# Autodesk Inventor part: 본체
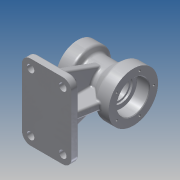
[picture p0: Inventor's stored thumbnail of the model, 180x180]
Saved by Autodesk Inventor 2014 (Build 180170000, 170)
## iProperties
Created: 2015-08
Part Number: 본체
Material: 알루미늄 6061
Document SubType Name: Modeling
Designer: SDA20
Density: 2.71 g/cm^3
Appearance: 알루미늄 - 평지
Mass: 1061.81 g
Surface Area: 751.05 cm^2
Volume: 391.813 cm^3
Author: SDA20
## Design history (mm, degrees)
sketch "스케치1"
  geometry: L1 (-574.06, -1.519)-(-484.06, -1.519); L2 (-574.06, -1.519)-(-574.06, 33.481); L3 (-574.06, 33.481)-(-554.06, 33.481); L4 (-554.06, 33.481)-(-548.864, 24.481); L5 (-548.864, 24.481)-(-520.745, 24.481); L6 (-520.745, 24.481)-(-504.06, 38.481); L7 (-504.06, 38.481)-(-484.06, 38.481); L8 (-484.06, 38.481)-(-484.06, -1.519)
  constraints: 16 end point, 3 parallel, 2 perpendicular, 1 horizontal
  dimensions: "d7" = 90 distance of L1.start L1.end; "d8" = 35 distance of L1.start L2.end; "d9" = 20 distance of L2.end L3.end; "d10" = 80 diameter of L7 L1; "d11" = 52 diameter of L5 L1; "d14" = 20 distance of L6.end L7.end
revolve "회전1" sketch "스케치1" stored, may be unused: angle "d17" = 90 deg
sketch "스케치2"
  geometry: C1 r 40 at (0, 0) reference; C2 r 26 at (0, 0)
  constraints: 1 centre point, 1 coincident
  dimensions: "d18" = 52 diameter of C2
extrude "돌출1" cut sketch "스케치2" distance "d19" = 20; taper "d20" = 0 deg
sketch "스케치3"
  geometry: C1 r 26 at (0, 0) reference; C2 r 19 at (0, 0)
  constraints: 1 centre point, 1 coincident
  dimensions: "d21" = 38 diameter of C2
extrude "돌출2" cut sketch "스케치3" distance "d22" = 3; taper "d23" = 0 deg
sketch "스케치4"
  geometry: C1 r 35 at (0, 0) reference; C2 r 20 at (0, 0)
  constraints: 1 centre point, 1 coincident
  dimensions: "d24" = 40 diameter of C2
extrude "돌출3" cut sketch "스케치4" distance "d25" = 17; taper "d26" = 0 deg
sketch "스케치5"
  geometry: C1 r 20 at (0, 0) reference; C2 r 16 at (0, 0)
  constraints: 1 centre point, 1 coincident
  dimensions: "d27" = 32 diameter of C2
extrude "돌출4" cut sketch "스케치5" stored distance "d28" = 17; taper "d29" = 0 deg
chamfer "모따기1" distance "d30" = 1; stored, may be unused: second distance "d31" = 2, angle "d32" = 45 deg
fillet "모깎기1" dims "d33" = 0.3
fillet "모깎기2" dims "d34" = 3
fillet "모깎기3" dims "d35" = 5
fillet "모깎기4" dims "d36" = 5
sketch "스케치6"
  geometry: L1 (0, 0)-(0, 27); C1 r 21 at (0, 0) reference; C2 r 27 at (0, 0)
  constraints: 2 end point, 1 centre point, 1 coincident, 1 vertical
  dimensions: "d37" = 54 diameter of C2; "d38" = 27 distance of L1.start L1.end
hole "구멍1" sketch "스케치6" at (0, 27) diameter "d39" = 3.459; stored, may be unused: countersink angle "d43" = 90 deg, drill point angle "d45" = 118 deg; dims "d40" = 10, "d41" = 4, "d42" = 2, "d44" = 13
sketch "스케치7"
  geometry: L1 (0, 0)-(0, 33); C1 r 27 at (0, 0) reference; C2 r 33 at (0, 0)
  constraints: 2 end point, 1 centre point, 1 coincident, 1 vertical
  dimensions: "d49" = 66 diameter of C2; "d50" = 33 distance of L1.start L1.end
hole "구멍2" sketch "스케치7" at (0, 33) diameter "d51" = 3.459; stored, may be unused: countersink angle "d55" = 90 deg, drill point angle "d57" = 118 deg; dims "d52" = 10, "d53" = 4, "d54" = 2, "d56" = 13
node "작업 평면1"
node "스케치8"
sketch "스케치9"
  geometry: L1 (-574.06, -36.519)-(-574.06, 33.481) reference; L2 (-574.06, -91.519)-(-494.06, -91.519); L3 (-494.06, -91.519)-(-494.06, -79.519); L4 (-494.06, -79.519)-(-574.06, -79.519); L5 (-574.06, -79.519)-(-574.06, -91.519)
  constraints: 8 end point, 2 perpendicular
  dimensions: "d62" = 80 distance of L2.start L2.end; "d63" = 12 distance of L2.end L3.end; "d64" = 80 distance of L3.end L4.end
extrude "돌출5" join sketch "스케치9" stored distance "d65" = 122; taper "d66" = 0 deg
node "작업 평면2"
sketch "스케치10"
  geometry: L1 (122, 12)-(122, 0) reference; L2 (122, 0)-(0, 0) reference; L3 (0, 0)-(0, 12) reference; L4 (0, 12)-(122, 12) reference; L5 (0, 12)-(10, 12); L6 (10, 12)-(37.923, 88.718); L7 (112, 12)-(84.077, 88.718); L8 (10, 12)-(112, 12); L9 (84.077, 88.718)-(71.095, 70.606); L10 (71.095, 70.606)-(51.998, 70.606); L11 (51.998, 70.606)-(37.923, 88.718); C1 r 26 at (61, 90) reference; C2 r 16 at (61, 90) reference
  constraints: 14 end point, 1 point on line
  dimensions: "d67" = 10 distance of L3.end L5.end; "d69" = 70 deg angle of L4 L6
extrude "돌출6" join sketch "스케치10" stored distance "d70" = 12; taper "d71" = 0 deg
node "작업 평면3"
sketch "스케치13"
  geometry: L1 (504.06, -27.219)-(504.06, -20.519) reference; L2 (504.06, -20.519)-(507.06, -20.519) reference; L3 (507.06, -20.519)-(507.06, -17.519) reference; L4 (507.06, -17.519)-(554.06, -17.519) reference; L5 (557.06, -20.519)-(557.06, -21.219) reference; L6 (557.36, -21.519)-(573.06, -21.519) reference; L7 (573.06, -21.519)-(574.06, -22.519) reference; L8 (574.06, -22.519)-(574.06, -36.519) reference; L9 (574.06, -36.519)-(556.947, -36.519) reference; L10 (552.617, -34.019)-(550.307, -30.019) reference; L11 (545.977, -27.519)-(540.06, -27.519) reference; L12 (540.06, -27.519)-(540.06, -79.519) reference; L13 (540.06, -79.519)-(574.06, -79.519) reference; L14 (574.06, -79.519)-(574.06, -91.519) reference; L15 (574.06, -91.519)-(494.06, -91.519) reference; L16 (494.06, -91.519)-(494.06, -79.519) reference; L17 (494.06, -79.519)-(528.06, -79.519) reference; L18 (528.06, -79.519)-(528.06, -27.519) reference; L19 (528.06, -27.519)-(522.564, -27.519) reference; L20 (519.351, -28.689)-(505.454, -40.349) reference; L21 (502.24, -41.519)-(484.06, -41.519) reference; L22 (484.06, -41.519)-(484.06, -28.519) reference; L23 (484.06, -28.519)-(485.06, -27.519) reference; L24 (485.06, -27.519)-(503.76, -27.519) reference; L25 (503.76, 24.481)-(485.06, 24.481) reference; L26 (485.06, 24.481)-(484.06, 25.481) reference; L27 (484.06, 25.481)-(484.06, 29.751) reference; L28 (484.06, 29.751)-(497.06, 29.751) reference; L29 (497.06, 29.751)-(498.099, 31.481) reference; L30 (498.099, 31.481)-(497.06, 33.21) reference; L31 (497.06, 33.21)-(484.06, 33.21) reference; L32 (484.06, 33.21)-(484.06, 38.481) reference; L33 (484.06, 38.481)-(502.24, 38.481) reference; L34 (505.454, 37.311)-(519.351, 25.651) reference; L35 (522.564, 24.481)-(545.977, 24.481) reference; L36 (550.307, 26.981)-(552.617, 30.981) reference; L37 (556.947, 33.481)-(574.06, 33.481) reference; L38 (574.06, 33.481)-(574.06, 27.21) reference; L39 (574.06, 27.21)-(561.06, 27.21) reference; L40 (561.06, 27.21)-(560.021, 25.481) reference; L41 (560.021, 25.481)-(561.06, 23.751) reference; L42 (561.06, 23.751)-(574.06, 23.751) reference; L43 (574.06, 23.751)-(574.06, 19.481) reference; L44 (574.06, 19.481)-(573.06, 18.481) reference; L45 (573.06, 18.481)-(557.36, 18.481) reference; L46 (557.06, 18.181)-(557.06, 17.481) reference; L47 (554.06, 14.481)-(507.06, 14.481) reference; L48 (507.06, 14.481)-(507.06, 17.481) reference; L49 (507.06, 17.481)-(504.06, 17.481) reference; L50 (504.06, 17.481)-(504.06, 24.181) reference; L51 (504.06, -79.519)-(496.122, -34.498); L52 (564.06, -79.519)-(564.06, -29.746); L53 (564.06, -29.746)-(543.395, -23.24); L54 (543.395, -23.24)-(519.98, -23.24); L55 (519.98, -23.24)-(496.122, -34.498); L56 (504.06, -79.519)-(564.06, -79.519); L57 (564.06, -29.746)-(564.06, -79.519); L58 (534.062, -23.24)-(534.06, -79.519); A1 r 0.3 centre (503.76, -27.219) between (503.76, -27.519) and (504.06, -27.219) reference; A2 r 3 centre (554.06, -20.519) between (557.06, -20.519) and (554.06, -17.519) reference; A3 r 0.3 centre (557.36, -21.219) between (557.06, -21.219) and (557.36, -21.519) reference; A4 r 5 centre (556.947, -31.519) between (552.617, -34.019) and (556.947, -36.519) reference; A5 r 5 centre (545.977, -32.519) between (550.307, -30.019) and (545.977, -27.519) reference; A6 r 5 centre (522.564, -32.519) between (522.564, -27.519) and (519.351, -28.689) reference; A7 r 5 centre (502.24, -36.519) between (502.24, -41.519) and (505.454, -40.349) reference; A8 r 0.3 centre (503.76, 24.181) between (504.06, 24.181) and (503.76, 24.481) reference; A9 r 5 centre (502.24, 33.481) between (505.454, 37.311) and (502.24, 38.481) reference; A10 r 5 centre (522.564, 29.481) between (519.351, 25.651) and (522.564, 24.481) reference; A11 r 5 centre (545.977, 29.481) between (545.977, 24.481) and (550.307, 26.981) reference; A12 r 5 centre (556.947, 28.481) between (556.947, 33.481) and (552.617, 30.981) reference; A13 r 0.3 centre (557.36, 18.181) between (557.36, 18.481) and (557.06, 18.181) reference; A14 r 3 centre (554.06, 17.481) between (554.06, 14.481) and (557.06, 17.481) reference
  constraints: 16 end point, 3 perpendicular, 3 point on line, 1 collinear, 1 midpoint
  dimensions: "d78" = 10 distance of L16.end L51.start; "d80" = 10 distance of L13.end L52.start
  node "절단 모서리 투영4"
node "스케치14"
extrude "돌출7" join sketch "스케치13" stored distance "d81" = 12; taper "d82" = 0 deg
sketch "스케치15"
  geometry: L1 (504.06, -27.219)-(504.06, -20.519) reference; L2 (504.06, -20.519)-(507.06, -20.519) reference; L3 (507.06, -20.519)-(507.06, -17.519) reference; L4 (507.06, -17.519)-(554.06, -17.519) reference; L5 (557.06, -20.519)-(557.06, -21.219) reference; L6 (557.36, -21.519)-(573.06, -21.519) reference; L7 (573.06, -21.519)-(574.06, -22.519) reference; L8 (574.06, -22.519)-(574.06, -36.519) reference; L9 (574.06, -36.519)-(556.947, -36.519) reference; L10 (552.617, -34.019)-(550.307, -30.019) reference; L11 (545.977, -27.519)-(540.06, -27.519) reference; L12 (540.06, -27.519)-(540.06, -79.519) reference; L13 (540.06, -79.519)-(574.06, -79.519) reference; L14 (574.06, -79.519)-(574.06, -91.519) reference; L15 (574.06, -91.519)-(494.06, -91.519) reference; L16 (494.06, -91.519)-(494.06, -79.519) reference; L17 (494.06, -79.519)-(504.06, -79.519) reference; L18 (485.06, -27.519)-(503.76, -27.519) reference; L19 (484.06, -28.519)-(485.06, -27.519) reference; L20 (484.06, -41.519)-(484.06, -28.519) reference; L21 (497.36, -41.519)-(484.06, -41.519) reference; L22 (503.76, 24.481)-(485.06, 24.481) reference; L23 (485.06, 24.481)-(484.06, 25.481) reference; L24 (484.06, 25.481)-(484.06, 29.751) reference; L25 (484.06, 29.751)-(497.06, 29.751) reference; L26 (497.06, 29.751)-(498.099, 31.481) reference; L27 (498.099, 31.481)-(497.06, 33.21) reference; L28 (497.06, 33.21)-(484.06, 33.21) reference; L29 (484.06, 33.21)-(484.06, 38.481) reference; L30 (484.06, 38.481)-(502.24, 38.481) reference; L31 (505.454, 37.311)-(519.351, 25.651) reference; L32 (522.564, 24.481)-(545.977, 24.481) reference; L33 (550.307, 26.981)-(552.617, 30.981) reference; L34 (556.947, 33.481)-(574.06, 33.481) reference; L35 (574.06, 33.481)-(574.06, 27.21) reference; L36 (574.06, 27.21)-(561.06, 27.21) reference; L37 (561.06, 27.21)-(560.021, 25.481) reference; L38 (560.021, 25.481)-(561.06, 23.751) reference; L39 (561.06, 23.751)-(574.06, 23.751) reference; L40 (574.06, 23.751)-(574.06, 19.481) reference; L41 (574.06, 19.481)-(573.06, 18.481) reference; L42 (573.06, 18.481)-(557.36, 18.481) reference; L43 (557.06, 18.181)-(557.06, 17.481) reference; L44 (554.06, 14.481)-(507.06, 14.481) reference; L45 (507.06, 14.481)-(507.06, 17.481) reference; L46 (507.06, 17.481)-(504.06, 17.481) reference; L47 (504.06, 17.481)-(504.06, 24.181) reference; L48 (574.06, -79.519)-(564.06, -79.519); L49 (564.06, -79.519)-(564.06, -29.137); L50 (564.06, -29.137)-(533.949, -20.063); L51 (533.949, -20.063)-(533.949, -79.519); L52 (564.06, -79.519)-(533.949, -79.519); L53 (504.06, -79.519)-(497.36, -41.519) reference; A1 r 0.3 centre (503.76, -27.219) between (503.76, -27.519) and (504.06, -27.219) reference; A2 r 3 centre (554.06, -20.519) between (557.06, -20.519) and (554.06, -17.519) reference; A3 r 0.3 centre (557.36, -21.219) between (557.06, -21.219) and (557.36, -21.519) reference; A4 r 5 centre (556.947, -31.519) between (552.617, -34.019) and (556.947, -36.519) reference; A5 r 5 centre (545.977, -32.519) between (550.307, -30.019) and (545.977, -27.519) reference; A6 r 0.3 centre (503.76, 24.181) between (504.06, 24.181) and (503.76, 24.481) reference; A7 r 5 centre (502.24, 33.481) between (505.454, 37.311) and (502.24, 38.481) reference; A8 r 5 centre (522.564, 29.481) between (519.351, 25.651) and (522.564, 24.481) reference; A9 r 5 centre (545.977, 29.481) between (545.977, 24.481) and (550.307, 26.981) reference; A10 r 5 centre (556.947, 28.481) between (556.947, 33.481) and (552.617, 30.981) reference; A11 r 0.3 centre (557.36, 18.181) between (557.36, 18.481) and (557.06, 18.181) reference; A12 r 3 centre (554.06, 17.481) between (554.06, 14.481) and (557.06, 17.481) reference
  constraints: 10 end point, 3 perpendicular, 1 point on line
  dimensions: "d83" = 10 distance of L13.end L48.end
extrude "돌출8" join sketch "스케치15" stored distance "d84" = 12; taper "d85" = 0 deg
fillet "모깎기5" dims "d86" = 3
fillet "모깎기6" dims "d87" = 3
fillet "모깎기7" dims "d88" = 3
sketch "스케치16"
  geometry: L1 (-52, 15)-(-52, 65.607) reference; L2 (-70, 65.607)-(-70, 15) reference; L3 (-107.716, 15)-(-70, 15) reference; L4 (-119, 12)-(-113.245, 12) reference; L5 (-122, 0)-(-122, 9) reference; L6 (0, 0)-(-122, 0) reference; L7 (0, 9)-(0, 0) reference; L8 (-8.755, 12)-(-3, 12) reference; L9 (-52, 15)-(-14.284, 15) reference; L10 (-14.284, 15)-(-37.519, 78.836) reference; L11 (-84.481, 78.836)-(-107.716, 15) reference; L12 (-61, 0)-(-61, 90); L13 (-37, 0)-(-37, 90); L14 (-85, 0)-(-37, 0); L15 (-79, 30)-(-79, 36); L16 (-91, 30)-(-91, 36); L17 (-43, 30)-(-43, 36); L18 (-31, 30)-(-31, 36); C1 r 16 at (-61, 90) reference; A1 r 26 centre (-61, 90) between (-52, 65.607) and (-37.519, 78.836) reference; A2 r 26 centre (-61, 90) between (-37.519, 78.836) and (-84.481, 78.836) reference; A3 r 26 centre (-61, 90) between (-84.481, 78.836) and (-70, 65.607) reference; A4 r 3 centre (-119, 9) between (-119, 12) and (-122, 9) reference; A5 r 3 centre (-3, 9) between (0, 9) and (-3, 12) reference; A6 r 6 centre (-85, 30) between (-91, 30) and (-79, 30); A7 r 6 centre (-85, 36) between (-79, 36) and (-91, 36); A8 r 6 centre (-37, 36) between (-31, 36) and (-43, 36); A9 r 6 centre (-37, 30) between (-43, 30) and (-31, 30)
  constraints: 14 end point, 8 point on circle, 6 symmetric about line, 4 centre point, 1 collinear, 1 midpoint, 1 parallel, 1 perpendicular, 4 other
  dimensions: "d90" = 24 distance between parallel lines of L13 L12; "d92" = 12 diameter of A6
extrude "돌출9" cut sketch "스케치16" distance "d98" = 30; taper "d99" = 0 deg
fillet "모깎기8" dims "d100" = 14
sketch "스케치17"
  geometry: C1 r 6 at (52, -11); C2 r 6 at (52, -105); C3 r 6 at (0, -11); C4 r 6 at (0, -105); A1 r 11 centre (52, -11) between (63, -11) and (52, 0) reference; A2 r 11 centre (0, -11) between (0, 0) and (-11, -11) reference; A3 r 11 centre (0, -105) between (-11, -105) and (0, -116) reference; A4 r 11 centre (52, -105) between (52, -116) and (63, -105) reference
  constraints: 4 centre point, 4 coincident
  dimensions: "d101" = 12 diameter of C1; "d102" = 12 diameter of C2; "d103" = 12 diameter of C3; "d104" = 12 diameter of C4
extrude "돌출10" cut sketch "스케치17" stored distance "d105" = 30; taper "d106" = 0 deg
fillet "모깎기9" dims "d107" = 3
sketch "스케치18"
  geometry: L1 (-504.06, 23.471)-(-504.06, 16.509) reference; L2 (-504.06, 16.509)-(-507.06, 16.509) reference; L3 (-507.06, 16.509)-(-507.06, 13.313) reference; L4 (-507.06, 13.313)-(-554.06, 13.313) reference; L5 (-557.06, 16.509)-(-557.06, 17.245) reference; L6 (-557.36, 17.56)-(-573.06, 17.56) reference; L7 (-574.06, 18.605)-(-574.06, 32.963) reference; L8 (-574.06, 32.963)-(-556.947, 32.963) reference; L9 (-545.977, 23.779)-(-522.564, 23.779) reference; L10 (-502.24, 38.028)-(-484.06, 38.028) reference; L11 (-484.06, 38.028)-(-484.06, 24.806) reference; L12 (-485.06, 23.779)-(-503.76, 23.779) reference; L13 (-503.76, -26.817)-(-485.06, -26.817) reference; L14 (-484.06, -27.844)-(-484.06, -41.067) reference; L15 (-484.06, -41.067)-(-495.864, -41.067) reference; L16 (-501.301, -79.519)-(-497.06, -79.519) reference; L17 (-494.06, -82.519)-(-494.06, -91.519) reference; L18 (-494.06, -91.519)-(-574.06, -91.519) reference; L19 (-574.06, -91.519)-(-574.06, -82.519) reference; L20 (-571.06, -79.519)-(-566.256, -79.519) reference; L21 (-561.06, -38.438)-(-561.06, -76.519) reference; L22 (-556.947, -38.438)-(-561.06, -38.438) reference; L23 (-543.06, -29.087)-(-545.977, -29.087) reference; L24 (-543.06, -76.519)-(-543.06, -29.087) reference; L25 (-561.06, -76.519)-(-543.06, -76.519) reference; L26 (-504.06, -19.547)-(-504.06, -26.509) reference; L27 (-507.06, -19.547)-(-504.06, -19.547) reference; L28 (-507.06, -16.352)-(-507.06, -19.547) reference; L29 (-554.06, -16.352)-(-507.06, -16.352) reference; L30 (-557.06, -20.283)-(-557.06, -19.547) reference; L31 (-573.06, -20.598)-(-557.36, -20.598) reference; L32 (-574.06, -36.001)-(-574.06, -21.644) reference; L33 (-565.923, -36.001)-(-574.06, -36.001) reference; L34 (-500.767, -43.567)-(-502.24, -43.567) reference; L35 (-522.564, -29.087)-(-525.06, -29.087) reference; L36 (-525.06, -29.087)-(-525.06, -76.519) reference; L37 (-525.06, -76.519)-(-506.577, -76.519) reference; L38 (-506.577, -76.519)-(-500.767, -43.567) reference; A1 r 3 centre (-497.06, -82.519) between (-494.06, -82.519) and (-497.06, -79.519) reference; A2 r 3 centre (-571.06, -82.519) between (-571.06, -79.519) and (-574.06, -82.519) reference; 9 further points
  constraints: 27 other
feature "엠보싱1" sketch "스케치18" dims "d7" = 90, "d8" = 35, "d9" = 20, "d10" = 80, "d11" = 52, "d14" = 20, "d112" = 0.5, "d113" = 0
node "솔리드1"
pattern_circular "원형 패턴1" dims angle "d47" = 360 deg
pattern_circular "원형 패턴2" dims angle "d59" = 360 deg
node "절단 모서리 투영1"
node "절단 모서리 투영5"
node "절단 모서리 투영6"
node "절단 모서리 투영7"
other parameters: "d95" = 12, "d96" = 6, "d97" = 6
